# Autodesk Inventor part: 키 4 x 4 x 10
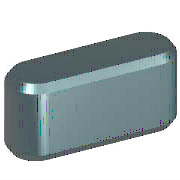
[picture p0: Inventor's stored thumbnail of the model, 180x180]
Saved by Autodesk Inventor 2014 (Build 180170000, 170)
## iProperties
IsCustomPart: 1
Created: 2012-02
Part Number: 키 4 x 4 x 10
Material: 강철, 연강
Description: 키 및 해당 키홈
Document SubType Name: Modeling
Standard: KS B 1311
Designer: test
Standards Organization: KS
Language: ko-KR
Size Designation: 4 x 4 x 10
Categories: <MemberInstance><Categories><Category DisplayName="샤프트 부품" InternalName="7f7aeb1f-a693-4053-b835-cee3144e0d98" Mnemonic="SHFT"><Category DisplayName="키" Interna
Density: 1 g/cm^3
Appearance: 노란색
Author: test
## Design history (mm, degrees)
workplane "Work Plane1"
workplane "Work Plane2"
sketch "스케치1"
  geometry: L1 (2, 2)-(8, 2); L2 (8, -2)-(2, -2); L3 (0, 9.4)-(0, -7.4) reference; L4 (-5, 0)-(30, 0) reference; L5 (10, 0)-(10, 7); A1 r 2 centre (2, 0) between (2, 2) and (2, -2); A2 r 2 centre (8, 0) between (8, -2) and (8, 2)
  constraints: 6 end point, 5 point on circle, 4 tangent, 3 point on line, 2 centre point, 1 horizontal, 1 parallel, 1 perpendicular
  dimensions: "d0" = 2 radius of A1 (= 0.5 x PB); "d13" = 2 radius of A2 (= 0.5 x PB); "d14" = 10 distance between parallel lines of L5 L3 (= NLG)
extrude "본체1" new body sketch "스케치1" taper "d3" = 0 deg; stored distance "d4" = 10
workplane "Work Plane3"
body "Solid1"
chamfer "모따기1" distance "d8" = 0.25 (= PHH); stored, may be unused: second distance "d9" = 0.25 (= PHH), angle "d15" = 45 deg
other parameters: "d1" = -2.5 (= -PNT), "d2" = 1.5 (= PH - PNT), "NLG" = 10 [user parameter; used in 3 equation terms], "PB" = 4 [user parameter; used in 2 equation terms], "PNT" = 2.5 [user parameter; used in 2 equation terms], "PH" = 4 [user parameter; used in 1 equation term], "PHH" = 0.25 [user parameter; used in 2 equation terms], "d10" = 0, "d16" = 0, "d17" = 0, "d18" = 0, "WDMAX" = 12 [user parameter], "RR" = 0.08 [user parameter], "PUEB" = 1.8 [user parameter]
